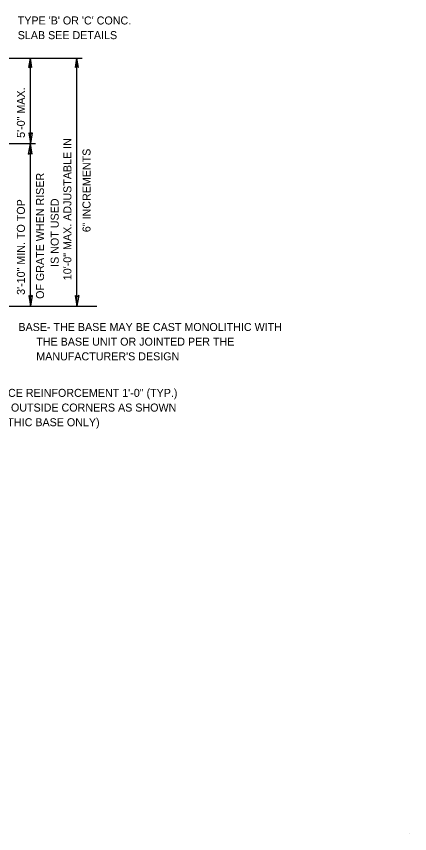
# Model space of a CAD drawing. Extents: x 4.74 to 11.91, y -5.26 to 4.54.
# Drawn here: x 8.97 to 11.91, y -5.26 to 0.86 of the extents above; entities that cross this region are included whole.
import ezdxf

# ---------------------------------------------------------------- set-up
doc = ezdxf.new("R2010")
doc.units = 0
for name, color, linetype in [('DETL-DIMS', 7, 'Continuous'), ('DETL-NOTE', 7, 'Continuous'), ('TTLB-TEXT', 7, 'Continuous')]:
    doc.layers.add(name, color=color, linetype=linetype)

msp = doc.modelspace()

# ---------------------------------------------------------------- linework, layer by layer
at = {"layer": 'DETL-DIMS'}
for p, q in [((8.6169, 0.5488), (9.4608, 0.5488)), ((9.0614, 0.4789), (9.0735, 0.5488)), ((9.0847, 0.4787), (9.0735, 0.5488)), ((9.0735, -0.091), (9.0735, 0.5488)), ((9.4097, 0.4789), (9.4217, 0.5488)), ((9.433, 0.4787), (9.4217, 0.5488)), ((9.4217, -1.3098), (9.4217, 0.5488)), ((9.0614, 0.4789), (9.0731, 0.4875)), ((9.0847, 0.4787), (9.0731, 0.4875)), ((9.4097, 0.4789), (9.4214, 0.4875)), ((9.433, 0.4787), (9.4214, 0.4875)), ((9.0606, -0.0109), (9.0735, -0.091)), ((9.0606, -0.0109), (9.0739, -0.021)), ((9.0872, -0.0111), (9.0735, -0.091)), ((9.0872, -0.0111), (9.0739, -0.021)), ((8.6152, -0.091), (9.1105, -0.091)), ((9.0597, -0.171), (9.0735, -0.091)), ((9.0735, -1.3098), (9.0735, -0.091)), ((9.0863, -0.1712), (9.0735, -0.091)), ((9.0597, -0.171), (9.073, -0.161)), ((9.0863, -0.1712), (9.073, -0.161)), ((9.0606, -1.2297), (9.0735, -1.3098)), ((9.0606, -1.2297), (9.0739, -1.2398)), ((9.0872, -1.2299), (9.0735, -1.3098)), ((9.0872, -1.2299), (9.0739, -1.2398)), ((9.4089, -1.2297), (9.4217, -1.3098)), ((9.4089, -1.2297), (9.4222, -1.2398)), ((9.4355, -1.2299), (9.4217, -1.3098)), ((9.4355, -1.2299), (9.4222, -1.2398)), ((8.612, -1.3098), (9.572, -1.3098))]:
    msp.add_line(p, q, dxfattribs=at)
at = {"layer": 'TTLB-TEXT'}
msp.add_line((11.9148, -5.2646), (11.9148, -5.2646), dxfattribs=at)

# ---------------------------------------------------------------- texts
at = {"layer": 'DETL-NOTE'}
for s, p in [("TYPE 'B' OR 'C' CONC.", (8.978, 0.8005)), ('SLAB SEE DETAILS', (8.978, 0.6905)), ('BASE- THE BASE MAY BE CAST MONOLITHIC WITH', (8.9832, -1.497)), ('      THE BASE UNIT OR JOINTED PER THE', (8.9832, -1.607)), ("      MANUFACTURER'S DESIGN", (8.9832, -1.717)), ('LAP SPLICE REINFORCEMENT 1\'-0" (TYP.)', (8.5573, -1.9909)), ('AROUND OUTSIDE CORNERS AS SHOWN', (8.5573, -2.1009)), ('(MONOLITHIC BASE ONLY)', (8.5573, -2.2109))]:
    msp.add_text(s, height=0.06, dxfattribs=at).set_placement(p)
for s, p in [('5\'-0" MAX.', (9.0318, -0.0494)), ('10\'-0" MAX. ADJUSTABLE IN', (9.38, -1.1164)), ('6" INCREMENTS', (9.5234, -0.7562)), ('OF GRATE WHEN RISER', (9.1751, -1.2563)), ('3\'-10" MIN. TO TOP', (9.0318, -1.2263)), ('IS NOT USED', (9.2851, -1.0163))]:
    msp.add_text(s, height=0.06, rotation=90, dxfattribs=at).set_placement(p)

doc.saveas('drawing.dxf')
